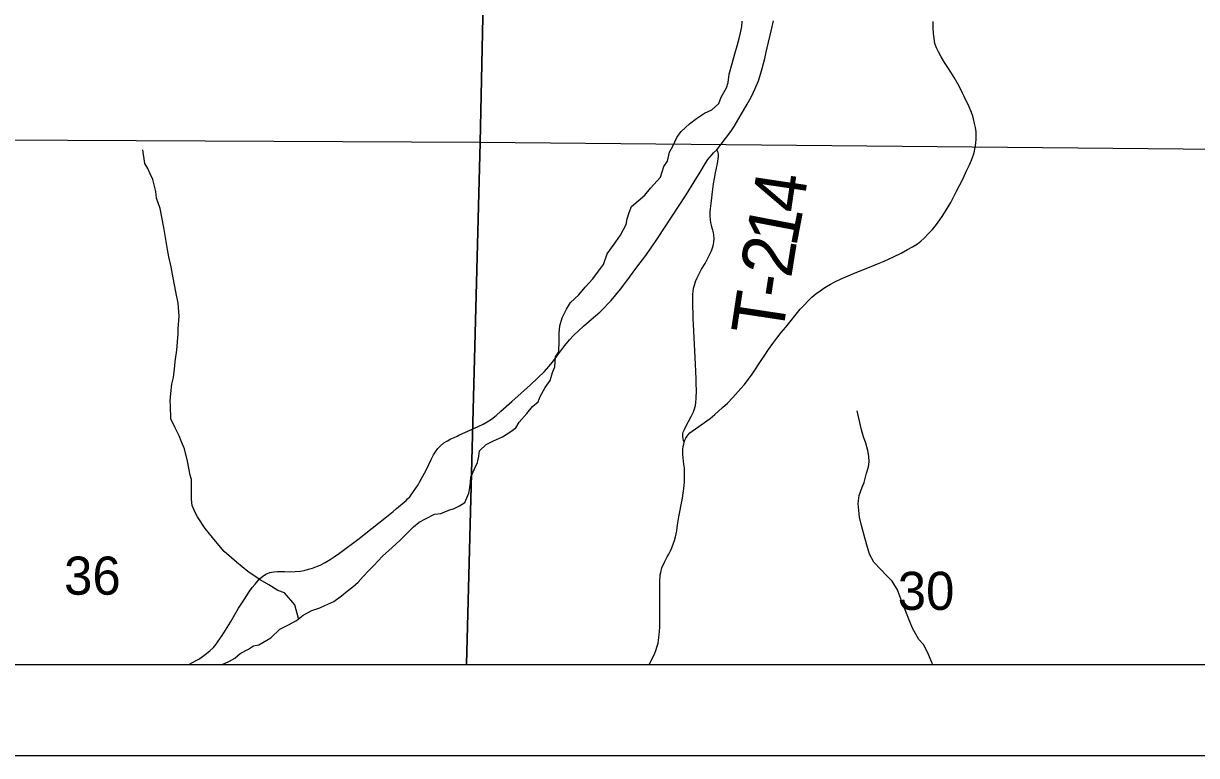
# Model space of a CAD drawing. Extents: x -1.2 to 34, y -8.5 to 22.
# Drawn here: x 5.742 to 7.031, y 14 to 14.804 of the extents above; entities that cross this region are included whole.
import ezdxf

# ---------------------------------------------------------------- set-up
doc = ezdxf.new("R2010")
doc.units = 0
for name, color, linetype in [('GM_X_Minor_River', 7, 'Continuous'), ('GM_X_Section', 7, 'Continuous'), ('GM_X_Section_Text', 7, 'Continuous'), ('GM_X_Township_Road', 7, 'Continuous'), ('GM_X_Township_Road_Text', 7, 'Continuous'), ('GM_X_Unincorporated_Text', 7, 'Continuous'), ('SH_Cut_Line', 7, 'Continuous'), ('SH_Data', 7, 'Continuous')]:
    doc.layers.add(name, color=color, linetype=linetype)

msp = doc.modelspace()

# ---------------------------------------------------------------- linework, layer by layer
at = {"layer": 'GM_X_Minor_River'}
for points in [[(6.1475, 14.2285), (6.1561, 14.2366), (6.1624, 14.2428), (6.1706, 14.2513), (6.177, 14.2563), (6.1841, 14.2599), (6.1939, 14.265), (6.2007, 14.2658), (6.2094, 14.2694), (6.2154, 14.2714), (6.2214, 14.2745), (6.227, 14.278), (6.2314, 14.2884), (6.2325, 14.2941), (6.2335, 14.3002), (6.2338, 14.3059), (6.2379, 14.3151), (6.2412, 14.322), (6.2426, 14.3289), (6.2433, 14.3346), (6.2507, 14.3416), (6.2586, 14.3459), (6.2684, 14.3502), (6.2766, 14.3553), (6.283, 14.3599), (6.2867, 14.3661), (6.2953, 14.3757), (6.3016, 14.3834), (6.3076, 14.3885), (6.3098, 14.3946), (6.3153, 14.4042), (6.3209, 14.4119), (6.3234, 14.4207), (6.3259, 14.4272), (6.3269, 14.4379), (6.3303, 14.4436), (6.3308, 14.4558), (6.3307, 14.4642), (6.3314, 14.4722), (6.3339, 14.481), (6.3387, 14.4906), (6.3431, 14.4979), (6.3524, 14.506), (6.3595, 14.5145), (6.3677, 14.5237), (6.374, 14.5322), (6.3796, 14.5395), (6.3836, 14.5514), (6.3929, 14.5644), (6.398, 14.5717), (6.4014, 14.5779), (6.4043, 14.5836), (6.4054, 14.5897), (6.4075, 14.5966), (6.4101, 14.6031), (6.425, 14.6155), (6.431, 14.6232), (6.4422, 14.6356), (6.4458, 14.6471), (6.4499, 14.6532), (6.452, 14.6631), (6.4557, 14.6697), (6.4601, 14.6792), (6.4649, 14.6858), (6.4739, 14.6939), (6.4817, 14.7001), (6.4904, 14.7059), (6.4986, 14.7095), (6.5061, 14.7165), (6.5087, 14.7233), (6.5146, 14.7337), (6.5164, 14.7394), (6.5177, 14.7486), (6.521, 14.7604), (6.5239, 14.7708), (6.5264, 14.7799), (6.5285, 14.788), (6.53, 14.7941), (6.5314, 14.8009), (6.5317, 14.8067)], [(5.9123, 14.4689), (5.9132, 14.4826), (5.9122, 14.4971), (5.9098, 14.5096), (5.9069, 14.5248), (5.9045, 14.5369), (5.902, 14.5479), (5.9004, 14.5559), (5.8979, 14.5714), (5.8966, 14.5802), (5.8926, 14.601), (5.8886, 14.6124), (5.8877, 14.6196), (5.8845, 14.6329), (5.8814, 14.6393), (5.879, 14.645), (5.8756, 14.6503), (5.8734, 14.6655)], [(6.0445, 14.1504), (6.0405, 14.1656), (6.029, 14.1788), (6.0217, 14.1813), (6.0118, 14.1876), (6.0023, 14.1932), (5.9889, 14.2021), (5.9762, 14.2126), (5.9628, 14.2242), (5.9532, 14.2354), (5.942, 14.2494), (5.9335, 14.2622), (5.9308, 14.2671), (5.9276, 14.2746), (5.9268, 14.2815), (5.927, 14.2925), (5.9268, 14.3032), (5.9256, 14.3081), (5.9224, 14.3233), (5.9191, 14.3369), (5.916, 14.3445), (5.9132, 14.3513), (5.9089, 14.36), (5.9043, 14.3698), (5.9037, 14.3843), (5.9036, 14.3892), (5.9042, 14.3976), (5.9052, 14.4079), (5.907, 14.4152), (5.9087, 14.4281), (5.909, 14.4331), (5.9107, 14.4453), (5.9124, 14.4636), (5.9123, 14.4689)], [(6.7412, 14.1), (6.74, 14.1022), (6.7356, 14.1128), (6.731, 14.1218), (6.726, 14.1275), (6.719, 14.1399), (6.7158, 14.1479), (6.7115, 14.1581), (6.7064, 14.171), (6.7024, 14.1819), (6.6966, 14.1914), (6.6909, 14.1974), (6.6843, 14.2045), (6.6766, 14.2124), (6.6716, 14.2214), (6.6684, 14.2324), (6.6656, 14.2431), (6.6628, 14.2529), (6.6608, 14.262), (6.6599, 14.2696), (6.6594, 14.2768), (6.6604, 14.2856), (6.6637, 14.2948), (6.6659, 14.3001), (6.6684, 14.3101), (6.6706, 14.317), (6.6712, 14.3227), (6.6711, 14.3288), (6.6699, 14.3352), (6.6675, 14.3432), (6.6652, 14.35), (6.6628, 14.358), (6.658, 14.3788)], [(5.9603, 14.1), (5.9631, 14.1012), (5.9687, 14.1036), (5.9744, 14.1071), (5.9803, 14.1122), (5.9894, 14.1169), (5.995, 14.1204), (6.001, 14.1216), (6.0142, 14.1294), (6.0239, 14.1387), (6.0336, 14.1434), (6.0423, 14.1485), (6.0494, 14.1543), (6.0592, 14.1594), (6.0678, 14.1622), (6.0735, 14.165), (6.0832, 14.1693), (6.0915, 14.1755), (6.0978, 14.1806), (6.1042, 14.1852), (6.1098, 14.1906), (6.1154, 14.1968), (6.1217, 14.2034), (6.1273, 14.2088), (6.1367, 14.2192), (6.1475, 14.2285)]]:
    msp.add_lwpolyline(points, dxfattribs=at)
at = {"layer": 'GM_X_Section'}
for points in [[(6.2657, 15.6908), (6.2441, 14.6736), (5.4125, 14.6774), (5.4262, 15.6104), (5.428, 15.6979)], [(7.2776, 15.674), (7.2479, 14.6639), (6.2441, 14.6736), (6.2657, 15.6908)], [(5.4061, 14.1), (6.2289, 14.1), (6.2441, 14.6736), (5.4125, 14.6774), (5.4116, 14.6095)], [(6.2289, 14.1), (7.2356, 14.1), (7.2479, 14.6639), (6.2441, 14.6736)]]:
    msp.add_lwpolyline(points, close=True, dxfattribs=at)
at = {"layer": 'GM_X_Township_Road'}
for points in [[(6.5038, 14.6656), (6.5183, 14.684), (6.5202, 14.6868), (6.523, 14.6912), (6.5372, 14.7157), (6.5416, 14.7235), (6.546, 14.7327), (6.5496, 14.7414), (6.5525, 14.7499), (6.5538, 14.7549), (6.5552, 14.7602), (6.5566, 14.7657), (6.5579, 14.7712), (6.5608, 14.7837), (6.5644, 14.799), (6.5663, 14.8073)], [(6.7655, 14.6164), (6.7673, 14.6199), (6.7741, 14.6333), (6.7787, 14.643), (6.7815, 14.6491), (6.7836, 14.6543), (6.7858, 14.66), (6.7869, 14.6641), (6.7878, 14.6684), (6.7885, 14.6726), (6.7889, 14.6774), (6.7887, 14.6851), (6.7881, 14.6902), (6.7872, 14.6946), (6.7859, 14.6997), (6.7848, 14.7034), (6.7831, 14.7082), (6.7812, 14.7127), (6.7758, 14.7242), (6.774, 14.7279), (6.7701, 14.7354), (6.7648, 14.7448), (6.761, 14.7509), (6.7578, 14.756), (6.7542, 14.7614), (6.7504, 14.7677), (6.7475, 14.7731), (6.7453, 14.7775), (6.7436, 14.7824), (6.7426, 14.7878), (6.7421, 14.7934), (6.7418, 14.7996), (6.7417, 14.8065)], [(6.2189, 14.351), (6.2206, 14.3518), (6.2418, 14.3614), (6.2472, 14.364), (6.2518, 14.3668), (6.2565, 14.3697), (6.2614, 14.3736), (6.2668, 14.3784), (6.2788, 14.389), (6.2992, 14.4074), (6.3074, 14.4151), (6.3145, 14.422), (6.3195, 14.4276), (6.3234, 14.4323), (6.3294, 14.4402), (6.3369, 14.4505), (6.3423, 14.4568), (6.347, 14.4617), (6.3519, 14.4667), (6.3576, 14.4718), (6.3686, 14.4811), (6.3754, 14.4872), (6.3803, 14.4919), (6.3844, 14.4962), (6.3878, 14.5001), (6.398, 14.5124), (6.4029, 14.5187), (6.4173, 14.538), (6.4248, 14.5479), (6.4319, 14.5578), (6.4389, 14.568), (6.4704, 14.616), (6.4792, 14.6302), (6.4855, 14.6408), (6.4917, 14.6508), (6.494, 14.6548), (6.4963, 14.6575), (6.4987, 14.6602), (6.5005, 14.6621), (6.5038, 14.6656)], [(6.4682, 14.3444), (6.4675, 14.3462), (6.4669, 14.3482), (6.4666, 14.35), (6.4665, 14.3519), (6.4666, 14.3537), (6.467, 14.3551), (6.4676, 14.3568), (6.4684, 14.3583), (6.4703, 14.3622), (6.473, 14.367), (6.4758, 14.3724), (6.4783, 14.3777), (6.4791, 14.3798), (6.4804, 14.3846), (6.4808, 14.3878), (6.4812, 14.3923), (6.4814, 14.3957), (6.4815, 14.3983), (6.4816, 14.4022), (6.4814, 14.4073), (6.4812, 14.4137), (6.4804, 14.43), (6.4782, 14.4737), (6.478, 14.4797), (6.4776, 14.4993), (6.4777, 14.5033), (6.4778, 14.5069), (6.4779, 14.51), (6.4784, 14.5135), (6.4794, 14.5168), (6.4806, 14.5208), (6.482, 14.5242), (6.4838, 14.5279), (6.4873, 14.5344), (6.491, 14.5406), (6.4946, 14.5472), (6.4979, 14.5538), (6.4986, 14.5557), (6.4996, 14.5589), (6.5002, 14.5616), (6.5006, 14.5644), (6.5009, 14.5676), (6.5008, 14.5722), (6.5004, 14.5744), (6.4995, 14.5772), (6.4989, 14.5796), (6.4981, 14.5826), (6.4973, 14.5857), (6.497, 14.5885), (6.4967, 14.5929), (6.4968, 14.5973), (6.4971, 14.6005), (6.4976, 14.6065), (6.4984, 14.6128), (6.4991, 14.6192), (6.5004, 14.6283), (6.5013, 14.6339), (6.5026, 14.6403), (6.5048, 14.6506), (6.5052, 14.6531), (6.5055, 14.6556), (6.5058, 14.658), (6.5059, 14.6602), (6.5053, 14.6626), (6.5046, 14.6642), (6.5038, 14.6656)], [(6.4682, 14.3444), (6.469, 14.3465), (6.47, 14.3488), (6.4713, 14.3508), (6.4726, 14.3525), (6.4744, 14.3544), (6.4768, 14.3563), (6.4805, 14.359), (6.4966, 14.3702), (6.5019, 14.3746), (6.5103, 14.3822), (6.5156, 14.3873), (6.5216, 14.3934), (6.5305, 14.4032), (6.5342, 14.4077), (6.5385, 14.4132), (6.5421, 14.418), (6.5473, 14.4257), (6.5498, 14.4296), (6.5534, 14.435), (6.5566, 14.4397), (6.5609, 14.446), (6.5656, 14.4527), (6.5699, 14.4586), (6.5747, 14.4648), (6.5797, 14.4708), (6.5956, 14.4903), (6.5999, 14.4947), (6.6043, 14.4995), (6.6082, 14.5036), (6.6128, 14.5074), (6.6174, 14.5107), (6.6226, 14.5143), (6.629, 14.518), (6.6345, 14.521), (6.6406, 14.5238), (6.6509, 14.5283), (6.656, 14.5305), (6.6737, 14.5372), (6.6822, 14.5408), (6.6878, 14.5433), (6.6979, 14.5479), (6.7064, 14.5521), (6.7134, 14.5558), (6.719, 14.5589), (6.7243, 14.5623), (6.728, 14.5652), (6.7322, 14.5689), (6.7363, 14.5731), (6.7408, 14.578), (6.7452, 14.5836), (6.7491, 14.5887), (6.7521, 14.5934), (6.755, 14.5981), (6.7609, 14.6077), (6.7655, 14.6164)], [(5.9374, 14.1077), (5.9391, 14.1088), (5.9435, 14.1121), (5.9474, 14.1153), (5.951, 14.1188), (5.9539, 14.1223), (5.9563, 14.1257), (5.9606, 14.132), (5.9696, 14.1466), (5.9787, 14.1619), (5.9852, 14.1717), (5.9903, 14.1797), (5.9935, 14.1845), (5.9968, 14.1884), (5.9997, 14.1918), (6.0021, 14.1946), (6.0048, 14.1968), (6.0087, 14.1992), (6.013, 14.201), (6.0174, 14.2019), (6.0215, 14.2022), (6.0292, 14.2021), (6.035, 14.2019), (6.0468, 14.2027), (6.0506, 14.2034), (6.0553, 14.2046), (6.0599, 14.206), (6.0654, 14.2081), (6.0681, 14.2093), (6.0738, 14.212), (6.0791, 14.2153), (6.0838, 14.2184), (6.0893, 14.2223), (6.1111, 14.2386), (6.1166, 14.2429), (6.141, 14.2621), (6.1483, 14.2681), (6.1521, 14.2714), (6.1626, 14.2802), (6.1643, 14.2819), (6.1666, 14.2843), (6.1682, 14.2864), (6.1758, 14.2975), (6.1775, 14.3004), (6.183, 14.3101), (6.1852, 14.3144), (6.1901, 14.3252), (6.1927, 14.3302), (6.1948, 14.3338), (6.1975, 14.3375), (6.2006, 14.3404), (6.2042, 14.3435), (6.2081, 14.3457), (6.2118, 14.3478), (6.2154, 14.3493), (6.2189, 14.351)], [(6.4295, 14.1), (6.4341, 14.1084), (6.436, 14.1123), (6.4371, 14.1154), (6.4385, 14.12), (6.4394, 14.1235), (6.4398, 14.1265), (6.4404, 14.13), (6.441, 14.136), (6.4412, 14.1419), (6.4414, 14.1524), (6.4415, 14.193), (6.4416, 14.1958), (6.4419, 14.1985), (6.4424, 14.2011), (6.4437, 14.2062), (6.4469, 14.2132), (6.4493, 14.2182), (6.4512, 14.2214), (6.453, 14.2249), (6.4544, 14.2282), (6.4563, 14.2332), (6.4573, 14.2364), (6.4584, 14.2402), (6.4592, 14.2437), (6.4599, 14.2469), (6.4605, 14.2505), (6.4612, 14.2555), (6.4622, 14.2621), (6.4658, 14.2809), (6.4661, 14.2827), (6.4681, 14.2962), (6.4686, 14.3013), (6.4684, 14.3128), (6.4683, 14.3157), (6.4678, 14.32), (6.4675, 14.3234), (6.4668, 14.3309), (6.4666, 14.3365), (6.4671, 14.3395), (6.4676, 14.342), (6.4682, 14.3444)], [(5.924, 14.1), (5.9321, 14.1044), (5.9349, 14.106), (5.9374, 14.1077)]]:
    msp.add_lwpolyline(points, dxfattribs=at)
at = {"layer": 'GM_X_Unincorporated_Text'}
msp.add_line((2.3586, 14.1), (8.2551, 14.1), dxfattribs=at)
at = {"layer": 'SH_Cut_Line'}
msp.add_lwpolyline([(2.3586, 14.1), (8.9, 14.1), (8.9, 17.6758), (8.3326, 17.6871), (7.9782, 17.6941), (7.8111, 17.6977), (7.3722, 17.707), (7.1254, 17.7122), (6.7322, 17.7204), (6.6751, 17.7216), (6.665, 17.7216)], dxfattribs=at)
at = {"layer": 'SH_Data'}
for p, q in [((2.1, 14.1), (8.9, 14.1)), ((2.1, 14.1), (8.9, 14.1)), ((2, 14), (9, 14)), ((2, 14), (9, 14))]:
    msp.add_line(p, q, dxfattribs=at)

# ---------------------------------------------------------------- texts
at = {"layer": 'GM_X_Section_Text'}
for s, p in [('36', (5.7869, 14.1767)), ('30', (6.7027, 14.16))]:
    msp.add_text(s, height=0.04186, rotation=0, dxfattribs=at).set_placement(p)
at = {"layer": 'GM_X_Township_Road_Text'}
for s, rotation, p in [('4', 81.5177, (6.598, 14.5945)), ('1', 79.1422, (6.591, 14.5576)), ('2', 80.8645, (6.5855, 14.5235)), ('-', 81.3025, (6.582, 14.5006)), ('T', 81.3881, (6.5757, 14.4586))]:
    msp.add_text(s, height=0.0568, rotation=rotation, dxfattribs=at).set_placement(p)

doc.saveas('drawing.dxf')
